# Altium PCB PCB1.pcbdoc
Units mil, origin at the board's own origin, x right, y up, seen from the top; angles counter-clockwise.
Board outline 1325 x 14900.2 mil, 2 copper layers (Top Layer, Bottom Layer); 150 components, 52 nets, 356 pads, 309 vias.
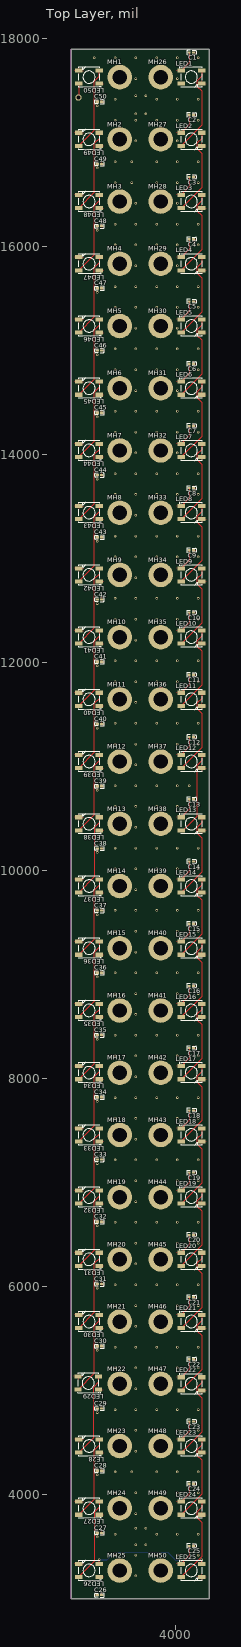
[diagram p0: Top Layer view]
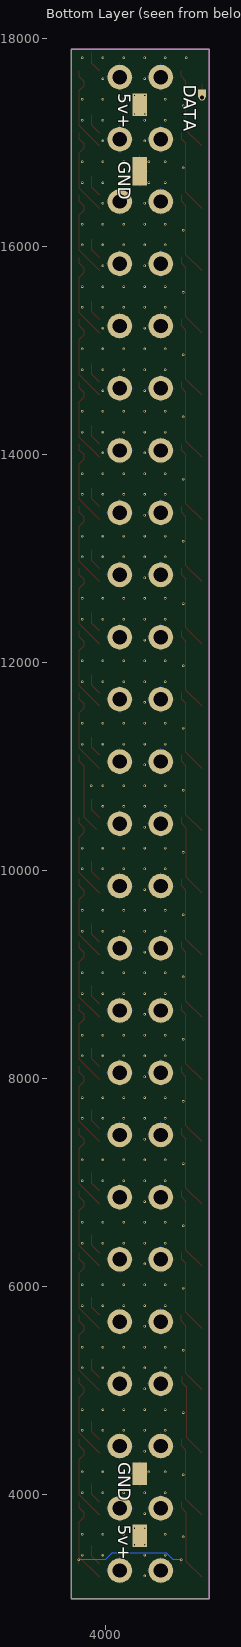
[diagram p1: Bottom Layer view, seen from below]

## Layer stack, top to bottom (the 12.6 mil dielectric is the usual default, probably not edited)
Top Layer: signal copper (thickness not stored)
Dielectric: dielectric 12.6, FR-4, Dk 4.8
Bottom Layer: signal copper (thickness not stored)

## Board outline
3000,17900.2 4325,17900.2 4325,3000 3000,3000

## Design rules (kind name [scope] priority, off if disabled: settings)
BoardOutlineClearance copperThickness1oz [All] p0: genericclearance=10 ignorepadtopadclearanceinfootprint=FALSE except(0: Arc-SplitContinuation Track-SplitContinuation SMDPad-SplitContinuation THPad-SplitContinuation Via-SplitContinuation Fill-SplitContinuation Poly-SplitContinuation Region-SplitContinuation Text-SplitContinuation; 6: Track-CutoutEdge SMDPad-CutoutEdge THPad-CutoutEdge Via-CutoutEdge Region-CutoutEdge; 11.8: Track-OutlineEdge SMDPad-OutlineEdge THPad-OutlineEdge Via-OutlineEdge Fill-OutlineEdge Region-OutlineEdge Poly-OutlineEdge Text-OutlineEdge Fill-CutoutEdge)
BoardOutlineClearance copperThickness2oz [All] p0: genericclearance=10 ignorepadtopadclearanceinfootprint=FALSE except(0: Arc-SplitContinuation Track-SplitContinuation SMDPad-SplitContinuation THPad-SplitContinuation Via-SplitContinuation Fill-SplitContinuation Poly-SplitContinuation Region-SplitContinuation Text-SplitContinuation; 6: Track-CutoutEdge SMDPad-CutoutEdge THPad-CutoutEdge Via-CutoutEdge Region-CutoutEdge; 11.8: Track-OutlineEdge SMDPad-OutlineEdge THPad-OutlineEdge Via-OutlineEdge Fill-OutlineEdge Region-OutlineEdge Poly-OutlineEdge Text-OutlineEdge Fill-CutoutEdge)
Clearance copperThickness1oz [(InNet('+5V') OR InNet('GND') OR InNet('$1N192') OR InNet('$1N362') OR InNet('$1N538') OR InNet('$1N3198') OR InNet('$1N3099') OR InNet('$1N3093') OR InNet('$1N3103') OR InNet('$1N3117') OR InNet('$1N3059') OR InNet('$1N3051') OR InNet('$1N3085') OR InNet('$1N3075') OR InNet('$1N3067') OR InNet('O1') OR InNet('$1N4231') OR InNet('$1N4177') OR InNet('$1N4173') OR InNet('$1N4275') OR InNet('$1N4261') OR InNet('$1N4249') OR InNet('$1N4241') OR InNet('$1N4215') OR InNet('$1N4197') OR InNet('$1N4191') OR InNet('$1N4223') OR InNet('$1N4207') OR InNet('O2') OR InNet('$1N5319') OR InNet('$1N5265') OR InNet('$1N5261') OR InNet('$1N5363') OR InNet('$1N5349') OR InNet('$1N5337') OR InNet('$1N5329') OR InNet('$1N5303') OR InNet('$1N5285') OR InNet('$1N5279') OR InNet('$1N5311') OR InNet('$1N5295') OR InNet('O3') OR InNet('$1N6407') OR InNet('$1N6353') OR InNet('$1N6349') OR InNet('$1N6451') OR InNet('$1N6437') OR InNet('$1N6431') OR InNet('$1N6425') OR InNet('DATA_IN') OR InNet('$1N11195') OR InNet('$1N11396'))] p1: gap=7 ignorepadtopadclearanceinfootprint=FALSE except(4: Track-Track; 6: Track-SMDPad SMDPad-SMDPad Track-THPad SMDPad-THPad THPad-THPad Track-Via SMDPad-Via THPad-Via Via-Via SMDPad-Fill THPad-Fill Via-Fill Fill-Fill Track-Region SMDPad-Region THPad-Region Via-Region Region-Region Track-Poly SMDPad-Poly THPad-Poly Via-Poly Fill-Poly Region-Poly Poly-Poly Track-Text SMDPad-Text THPad-Text Via-Text Fill-Text Region-Text Poly-Text Text-Text; 6.9: Track-Hole SMDPad-Hole THPad-Hole Via-Hole Fill-Hole Region-Hole Poly-Hole Text-Hole Sheet-Hole; 11.8: Track-Fill Fill-Region Track-Sheet SMDPad-Sheet THPad-Sheet Via-Sheet Fill-Sheet Region-Sheet Poly-Sheet Text-Sheet)
Clearance copperThickness2oz [All] p1: gap=7 ignorepadtopadclearanceinfootprint=FALSE except(6: Track-SMDPad SMDPad-SMDPad Track-THPad SMDPad-THPad THPad-THPad Track-Via SMDPad-Via THPad-Via Via-Via SMDPad-Fill THPad-Fill Via-Fill Fill-Fill Track-Region SMDPad-Region THPad-Region Via-Region Region-Region Track-Poly SMDPad-Poly THPad-Poly Via-Poly Fill-Poly Region-Poly Poly-Poly Track-Text SMDPad-Text THPad-Text Via-Text Fill-Text Region-Text Poly-Text Text-Text; 6.9: Track-Hole SMDPad-Hole THPad-Hole Via-Hole Fill-Hole Region-Hole Poly-Hole Text-Hole Sheet-Hole; 8: Track-Track; 11.8: Track-Fill Fill-Region Track-Sheet SMDPad-Sheet THPad-Sheet Via-Sheet Fill-Sheet Region-Sheet Poly-Sheet Text-Sheet)
DiffPairsRouting differentialPair [All] p1: maxuncoupledlength=10 minlimit=6 maxlimit=6 mostfreqgap=6 toplayer_minwidth=5 toplayer_prefwidth=10 toplayer_maxwidth=100 bottomlayer_minwidth=5 bottomlayer_prefwidth=10 bottomlayer_maxwidth=100
PasteMaskExpansion pasteMaskExpansion [All] p1: expansion=0
PlaneConnect innerPlane [All] p1: planeconnectstyle=Relief reliefexpansion=20 reliefentries=4 reliefconductorwidth=10 reliefairgap=10
PolygonConnect copperRegion [All] p1: connectstyle=Relief reliefentries=4 reliefconductorwidth=10 polygonreliefangle="90 Angle" airgapwidth=10
RoutingVias viaSize [All] p1: viastyle="Through Hole" holewidth=12.0078 minholewidth=11.811 maxholewidth=248.0314 width=24.0158 minwidth=19.685 maxwidth=393.7008
SolderMaskExpansion solderMaskExpansion [All] p1: useseparateexpansions=TRUE expansion=2 expansionbottom=2
Width copperThickness1oz [All] p1: maxlimit=100 minlimit=5 preferedwidth=10
Width copperThickness2oz [All] p1: maxlimit=100 minlimit=8 preferedwidth=10

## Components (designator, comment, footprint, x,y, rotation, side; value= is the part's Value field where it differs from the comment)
C1 "CC0402KRX7R7BB104" C0402 4154.41,17869.42 r180 top
C2 "CC0402KRX7R7BB104" C0402 4154.41,17270.97 r180 top
C3 "CC0402KRX7R7BB104" C0402 4154.44,16672.57 r180 top
C4 "CC0402KRX7R7BB104" C0402 4154.41,16074.07 r180 top
C5 "CC0402KRX7R7BB104" C0402 4154.41,15475.62 r180 top
C6 "CC0402KRX7R7BB104" C0402 4154.44,14877.29 r180 top
C7 "CC0402KRX7R7BB104" C0402 4154.44,14278.87 r180 top
C8 "CC0402KRX7R7BB104" C0402 4154.44,13680.44 r180 top
C9 "CC0402KRX7R7BB104" C0402 4154.44,13082.02 r180 top
C10 "CC0402KRX7R7BB104" C0402 4154.44,12483.59 r180 top
C11 "CC0402KRX7R7BB104" C0402 4154.41,11884.91 r180 top
C12 "CC0402KRX7R7BB104" C0402 4154.41,11286.46 r180 top
C13 "CC0402KRX7R7BB104" C0402 4154.41,10688.01 r180 top
C14 "CC0402KRX7R7BB104" C0402 4154.41,10089.56 r180 top
C15 "CC0402KRX7R7BB104" C0402 4154.44,9491.46 r180 top
C16 "CC0402KRX7R7BB104" C0402 4154.44,8893.04 r180 top
C17 "CC0402KRX7R7BB104" C0402 4154.44,8294.61 r180 top
C18 "CC0402KRX7R7BB104" C0402 4154.41,7695.76 r180 top
C19 "CC0402KRX7R7BB104" C0402 4154.41,7097.31 r180 top
C20 "CC0402KRX7R7BB104" C0402 4154.41,6498.86 r180 top
C21 "CC0402KRX7R7BB104" C0402 4154.41,5900.41 r180 top
C22 "CC0402KRX7R7BB104" C0402 4154.44,5302.49 r180 top
C23 "CC0402KRX7R7BB104" C0402 4154.44,4704.06 r180 top
C24 "CC0402KRX7R7BB104" C0402 4154.44,4105.64 r180 top
C25 "CC0402KRX7R7BB104" C0402 4154.44,3507.21 r180 top
C26 "CC0402KRX7R7BB104" C0402 3270.25,3034.17 r0 top
C27 "CC0402KRX7R7BB104" C0402 3270.25,3632.62 r0 top
C28 "CC0402KRX7R7BB104" C0402 3270.25,4231.07 r0 top
C29 "CC0402KRX7R7BB104" C0402 3270.25,4829.52 r0 top
C30 "CC0402KRX7R7BB104" C0402 3270.25,5427.97 r0 top
C31 "CC0402KRX7R7BB104" C0402 3270.25,6026.42 r0 top
C32 "CC0402KRX7R7BB104" C0402 3270.25,6624.87 r0 top
C33 "CC0402KRX7R7BB104" C0402 3270.25,7223.32 r0 top
C34 "CC0402KRX7R7BB104" C0402 3270.25,7821.77 r0 top
C35 "CC0402KRX7R7BB104" C0402 3270.25,8420.22 r0 top
C36 "CC0402KRX7R7BB104" C0402 3270.25,9018.67 r0 top
C37 "CC0402KRX7R7BB104" C0402 3270.25,9617.12 r0 top
C38 "CC0402KRX7R7BB104" C0402 3270.25,10215.57 r0 top
C39 "CC0402KRX7R7BB104" C0402 3270.25,10814.02 r0 top
C40 "CC0402KRX7R7BB104" C0402 3270.25,11412.47 r0 top
C41 "CC0402KRX7R7BB104" C0402 3270.25,12010.92 r0 top
C42 "CC0402KRX7R7BB104" C0402 3270.25,12609.37 r0 top
C43 "CC0402KRX7R7BB104" C0402 3270.25,13207.82 r0 top
C44 "CC0402KRX7R7BB104" C0402 3270.25,13806.27 r0 top
C45 "CC0402KRX7R7BB104" C0402 3270.25,14404.72 r0 top
C46 "CC0402KRX7R7BB104" C0402 3270.25,15003.17 r0 top
C47 "CC0402KRX7R7BB104" C0402 3270.25,15601.63 r0 top
C48 "CC0402KRX7R7BB104" C0402 3270.25,16200.08 r0 top
C49 "CC0402KRX7R7BB104" C0402 3270.25,16798.53 r0 top
C50 "CC0402KRX7R7BB104" C0402 3270.25,17396.98 r0 top
LE28 "WS2812B-V5/W" LED-SMD_4P-L5.0-W5.0-TL-1 3170.2,4468.4 r180 top
LED1 "WS2812B-V5/W" LED-SMD_4P-L5.0-W5.0-TL-1 4154.39,17633.2 r0 top
LED2 "WS2812B-V5/W" LED-SMD_4P-L5.0-W5.0-TL-1 4154.39,17034.8 r0 top
LED3 "WS2812B-V5/W" LED-SMD_4P-L5.0-W5.0-TL-1 4154.39,16436.4 r0 top
LED4 "WS2812B-V5/W" LED-SMD_4P-L5.0-W5.0-TL-1 4154.39,15838 r0 top
LED5 "WS2812B-V5/W" LED-SMD_4P-L5.0-W5.0-TL-1 4154.39,15239.6 r0 top
LED6 "WS2812B-V5/W" LED-SMD_4P-L5.0-W5.0-TL-1 4154.39,14641.2 r0 top
LED7 "WS2812B-V5/W" LED-SMD_4P-L5.0-W5.0-TL-1 4154.39,14042.8 r0 top
LED8 "WS2812B-V5/W" LED-SMD_4P-L5.0-W5.0-TL-1 4154.39,13444.4 r0 top
LED9 "WS2812B-V5/W" LED-SMD_4P-L5.0-W5.0-TL-1 4154.39,12846 r0 top
LED10 "WS2812B-V5/W" LED-SMD_4P-L5.0-W5.0-TL-1 4154.39,12247.6 r0 top
LED11 "WS2812B-V5/W" LED-SMD_4P-L5.0-W5.0-TL-1 4154.39,11649.2 r0 top
LED12 "WS2812B-V5/W" LED-SMD_4P-L5.0-W5.0-TL-1 4154.39,11050.8 r0 top
LED13 "WS2812B-V5/W" LED-SMD_4P-L5.0-W5.0-TL-1 4154.39,10452.4 r0 top
LED14 "WS2812B-V5/W" LED-SMD_4P-L5.0-W5.0-TL-1 4154.39,9854 r0 top
LED15 "WS2812B-V5/W" LED-SMD_4P-L5.0-W5.0-TL-1 4154.39,9255.6 r0 top
LED16 "WS2812B-V5/W" LED-SMD_4P-L5.0-W5.0-TL-1 4154.39,8657.2 r0 top
LED17 "WS2812B-V5/W" LED-SMD_4P-L5.0-W5.0-TL-1 4154.39,8058.8 r0 top
LED18 "WS2812B-V5/W" LED-SMD_4P-L5.0-W5.0-TL-1 4154.39,7460.4 r0 top
LED19 "WS2812B-V5/W" LED-SMD_4P-L5.0-W5.0-TL-1 4154.39,6862 r0 top
LED20 "WS2812B-V5/W" LED-SMD_4P-L5.0-W5.0-TL-1 4154.39,6263.6 r0 top
LED21 "WS2812B-V5/W" LED-SMD_4P-L5.0-W5.0-TL-1 4154.39,5665.2 r0 top
LED22 "WS2812B-V5/W" LED-SMD_4P-L5.0-W5.0-TL-1 4154.39,5066.8 r0 top
LED23 "WS2812B-V5/W" LED-SMD_4P-L5.0-W5.0-TL-1 4154.39,4468.4 r0 top
LED24 "WS2812B-V5/W" LED-SMD_4P-L5.0-W5.0-TL-1 4154.39,3870 r0 top
LED25 "WS2812B-V5/W" LED-SMD_4P-L5.0-W5.0-TL-1 4154.39,3271.6 r0 top
LED26 "WS2812B-V5/W" LED-SMD_4P-L5.0-W5.0-TL-1 3170.2,3271.6 r180 top
LED27 "WS2812B-V5/W" LED-SMD_4P-L5.0-W5.0-TL-1 3170.2,3870 r180 top
LED29 "WS2812B-V5/W" LED-SMD_4P-L5.0-W5.0-TL-1 3162.77,5074.23 r180 top
LED30 "WS2812B-V5/W" LED-SMD_4P-L5.0-W5.0-TL-1 3170.2,5665.2 r180 top
LED31 "WS2812B-V5/W" LED-SMD_4P-L5.0-W5.0-TL-1 3170.2,6263.6 r180 top
LED32 "WS2812B-V5/W" LED-SMD_4P-L5.0-W5.0-TL-1 3170.2,6862 r180 top
LED33 "WS2812B-V5/W" LED-SMD_4P-L5.0-W5.0-TL-1 3170.2,7460.4 r180 top
LED34 "WS2812B-V5/W" LED-SMD_4P-L5.0-W5.0-TL-1 3170.2,8058.8 r180 top
LED35 "WS2812B-V5/W" LED-SMD_4P-L5.0-W5.0-TL-1 3170.2,8657.2 r180 top
LED36 "WS2812B-V5/W" LED-SMD_4P-L5.0-W5.0-TL-1 3170.2,9255.6 r180 top
LED37 "WS2812B-V5/W" LED-SMD_4P-L5.0-W5.0-TL-1 3170.2,9854 r180 top
LED38 "WS2812B-V5/W" LED-SMD_4P-L5.0-W5.0-TL-1 3170.2,10452.4 r180 top
LED39 "WS2812B-V5/W" LED-SMD_4P-L5.0-W5.0-TL-1 3170.2,11050.8 r180 top
LED40 "WS2812B-V5/W" LED-SMD_4P-L5.0-W5.0-TL-1 3170.2,11649.2 r180 top
LED41 "WS2812B-V5/W" LED-SMD_4P-L5.0-W5.0-TL-1 3170.2,12247.6 r180 top
LED42 "WS2812B-V5/W" LED-SMD_4P-L5.0-W5.0-TL-1 3170.2,12846 r180 top
LED43 "WS2812B-V5/W" LED-SMD_4P-L5.0-W5.0-TL-1 3170.2,13444.4 r180 top
LED44 "WS2812B-V5/W" LED-SMD_4P-L5.0-W5.0-TL-1 3170.2,14042.8 r180 top
LED45 "WS2812B-V5/W" LED-SMD_4P-L5.0-W5.0-TL-1 3170.2,14641.2 r180 top
LED46 "WS2812B-V5/W" LED-SMD_4P-L5.0-W5.0-TL-1 3170.2,15239.6 r180 top
LED47 "WS2812B-V5/W" LED-SMD_4P-L5.0-W5.0-TL-1 3170.2,15838 r180 top
LED48 "WS2812B-V5/W" LED-SMD_4P-L5.0-W5.0-TL-1 3170.2,16436.4 r180 top
LED49 "WS2812B-V5/W" LED-SMD_4P-L5.0-W5.0-TL-1 3170.2,17034.8 r180 top
LED50 "WS2812B-V5/W" LED-SMD_4P-L5.0-W5.0-TL-1 3170.28,17633.07 r180 top
MH1 "M3_Hole" M3_Hole 3465.55,17633.07 r0 top
MH2 "M3_Hole" M3_Hole 3465.55,17034.65 r0 top
MH3 "M3_Hole" M3_Hole 3465.55,16436.22 r0 top
MH4 "M3_Hole" M3_Hole 3465.55,15837.8 r0 top
MH5 "M3_Hole" M3_Hole 3465.55,15239.37 r0 top
MH6 "M3_Hole" M3_Hole 3465.55,14640.94 r0 top
MH7 "M3_Hole" M3_Hole 3465.55,14042.52 r0 top
MH8 "M3_Hole" M3_Hole 3465.55,13444.09 r0 top
MH9 "M3_Hole" M3_Hole 3465.55,12845.67 r0 top
MH10 "M3_Hole" M3_Hole 3465.55,12247.24 r0 top
MH11 "M3_Hole" M3_Hole 3465.55,11648.82 r0 top
MH12 "M3_Hole" M3_Hole 3465.55,11050.39 r0 top
MH13 "M3_Hole" M3_Hole 3465.55,10451.97 r0 top
MH14 "M3_Hole" M3_Hole 3465.55,9853.54 r0 top
MH15 "M3_Hole" M3_Hole 3465.55,9255.12 r0 top
MH16 "M3_Hole" M3_Hole 3465.55,8656.69 r0 top
MH17 "M3_Hole" M3_Hole 3465.55,8058.27 r0 top
MH18 "M3_Hole" M3_Hole 3465.55,7459.84 r0 top
MH19 "M3_Hole" M3_Hole 3465.55,6861.42 r0 top
MH20 "M3_Hole" M3_Hole 3465.55,6262.99 r0 top
MH21 "M3_Hole" M3_Hole 3465.55,5664.57 r0 top
MH22 "M3_Hole" M3_Hole 3465.55,5066.14 r0 top
MH23 "M3_Hole" M3_Hole 3465.55,4467.72 r0 top
MH24 "M3_Hole" M3_Hole 3465.55,3869.29 r0 top
MH25 "M3_Hole" M3_Hole 3465.55,3270.87 r0 top
MH26 "M3_Hole" M3_Hole 3859.25,17633.07 r0 top
MH27 "M3_Hole" M3_Hole 3859.25,17034.65 r0 top
MH28 "M3_Hole" M3_Hole 3859.25,16436.22 r0 top
MH29 "M3_Hole" M3_Hole 3859.25,15837.8 r0 top
MH30 "M3_Hole" M3_Hole 3859.25,15239.37 r0 top
MH31 "M3_Hole" M3_Hole 3859.25,14640.94 r0 top
MH32 "M3_Hole" M3_Hole 3859.25,14042.52 r0 top
MH33 "M3_Hole" M3_Hole 3859.25,13444.09 r0 top
MH34 "M3_Hole" M3_Hole 3859.25,12845.67 r0 top
MH35 "M3_Hole" M3_Hole 3859.25,12247.24 r0 top
MH36 "M3_Hole" M3_Hole 3859.25,11648.82 r0 top
MH37 "M3_Hole" M3_Hole 3859.25,11050.39 r0 top
MH38 "M3_Hole" M3_Hole 3859.25,10451.97 r0 top
MH39 "M3_Hole" M3_Hole 3859.25,9853.54 r0 top
MH40 "M3_Hole" M3_Hole 3859.25,9255.12 r0 top
MH41 "M3_Hole" M3_Hole 3859.25,8656.69 r0 top
MH42 "M3_Hole" M3_Hole 3859.25,8058.27 r0 top
MH43 "M3_Hole" M3_Hole 3859.25,7459.84 r0 top
MH44 "M3_Hole" M3_Hole 3859.25,6861.42 r0 top
MH45 "M3_Hole" M3_Hole 3859.25,6262.99 r0 top
MH46 "M3_Hole" M3_Hole 3859.25,5664.57 r0 top
MH47 "M3_Hole" M3_Hole 3859.25,5066.14 r0 top
MH48 "M3_Hole" M3_Hole 3859.25,4467.72 r0 top
MH49 "M3_Hole" M3_Hole 3859.25,3869.29 r0 top
MH50 "M3_Hole" M3_Hole 3859.25,3270.87 r0 top

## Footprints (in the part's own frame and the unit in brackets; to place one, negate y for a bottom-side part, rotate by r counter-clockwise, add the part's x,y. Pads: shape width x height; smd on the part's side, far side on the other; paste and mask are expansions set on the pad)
C0402 [mm]
  rect 0.79x0.54 smd: 1(-0.545,0) 2(0.545,0)
  silkscreen extent -1.17,-0.5 1.17,0.5
LED-SMD_4P-L5.0-W5.0-TL-1 [mm]
  rect 1.8x1 smd: 1(-2.5,1.6) 2(-2.5,-1.6) 3(2.5,-1.6) 4(2.5,1.6)
  silkscreen extent -3,-2.5 2.51,2.5
M3_Hole [mm]
  round 6 hole 3.5: 1(0,0)

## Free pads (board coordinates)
  round 60 hole 36: 1(3067.91,17436.23)
  rect 78.74x78.74 smd far side: 1(3067.91,17475.6)
  rect 137.79x216.53 smd far side: 2(3668.3,3603.55) 2(3668.3,4201.98) 2(3668.3,17367.33)
  rect 137.79x275.59 smd far side: 5(3668.3,16727.57)

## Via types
v1: diameter 24.02, hole 12.01, Top Layer to Bottom Layer, 309 vias

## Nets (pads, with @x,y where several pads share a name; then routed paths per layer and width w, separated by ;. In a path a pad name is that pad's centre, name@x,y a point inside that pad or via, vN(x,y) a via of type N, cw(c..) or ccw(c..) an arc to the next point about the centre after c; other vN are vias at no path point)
$1N192: LED1.4 LED2.2 | length 844.4
  Top Layer w10: LED2.2 4252.81,17168.66 4252.81,17499.55 4206.4,17545.97 4206.4,17594.44 4252.81,17640.86 LED1.4
$1N362: LED2.4 LED3.2 | length 844.4
  Top Layer w10: LED3.2 4252.81,16570.26 4252.81,16901.15 4206.4,16947.57 4206.4,16996.04 4252.81,17042.46 LED2.4
$1N538: LED3.4 LED4.2 | length 844.4
  Top Layer w10: LED4.2 4252.81,15971.86 4252.81,16302.75 4206.4,16349.17 4206.4,16397.64 4252.81,16444.06 LED3.4
$1N3051: LED10.4 LED11.2 | length 844.4
  Top Layer w10: LED11.2 4252.81,11783.06 4252.81,12113.95 4206.4,12160.37 4206.4,12208.84 4252.81,12255.26 LED10.4
$1N3059: LED9.4 LED10.2 | length 844.4
  Top Layer w10: LED10.2 4252.81,12381.46 4252.81,12712.35 4206.4,12758.77 4206.4,12807.24 4252.81,12853.66 LED9.4
$1N3067: LED13.4 LED14.2 | length 844.4
  Top Layer w10: LED14.2 4252.81,9987.86 4252.81,10318.75 4206.4,10365.17 4206.4,10413.64 4252.81,10460.06 LED13.4
$1N3075: LED12.4 LED13.2 | length 782.8
  Top Layer w10: LED13.2@4085.79,10400.2 4206.4,10520.8 4206.4,11012.04 4252.81,11058.46 LED12.4
$1N3085: LED11.4 LED12.2 | length 844.4
  Top Layer w10: LED12.2 4252.81,11184.66 4252.81,11515.55 4206.4,11561.97 4206.4,11610.44 4252.81,11656.86 LED11.4
$1N3093: LED6.4 LED7.2 | length 844.4
  Top Layer w10: LED7.2 4252.81,14176.66 4252.81,14507.55 4206.4,14553.97 4206.4,14602.44 4252.81,14648.86 LED6.4
$1N3099: LED5.4 LED6.2 | length 844.4
  Top Layer w10: LED6.2 4252.81,14775.06 4252.81,15105.95 4206.4,15152.37 4206.4,15200.84 4252.81,15247.26 LED5.4
$1N3103: LED7.4 LED8.2 | length 844.4
  Top Layer w10: LED8.2 4252.81,13578.26 4252.81,13909.15 4206.4,13955.57 4206.4,14004.04 4252.81,14050.46 LED7.4
$1N3117: LED8.4 LED9.2 | length 844.4
  Top Layer w10: LED9.2 4252.81,12979.86 4252.81,13310.75 4206.4,13357.17 4206.4,13405.64 4252.81,13452.06 LED8.4
$1N3198: LED4.4 LED5.2 | length 844.4
  Top Layer w10: LED5.2 4252.81,15373.46 4252.81,15704.35 4206.4,15750.77 4206.4,15799.24 4252.81,15845.66 LED4.4
$1N4173: LED17.4 LED18.2 | length 844.4
  Top Layer w10: LED18.2 4252.81,7594.26 4252.81,7925.15 4206.4,7971.57 4206.4,8020.04 4252.81,8066.46 LED17.4
$1N4177: LED16.4 LED17.2 | length 844.4
  Top Layer w10: LED17.2 4252.81,8192.66 4252.81,8523.55 4206.4,8569.97 4206.4,8618.44 4252.81,8664.86 LED16.4
$1N4191: LED24.4 LED25.2 | length 844.4
  Top Layer w10: LED25.2 4252.81,3405.46 4252.81,3736.35 4206.4,3782.77 4206.4,3831.24 4252.81,3877.66 LED24.4
$1N4197: LED23.4 LED24.2 | length 844.4
  Top Layer w10: LED24.2 4252.81,4003.86 4252.81,4334.75 4206.4,4381.17 4206.4,4429.64 4252.81,4476.06 LED23.4
$1N4207: LED25.4 LED26.2 | length 1119.7
  Top Layer w10: LED26.2 v1(3268.62,3373.96) ; LED25.4 4252.81,3372.94 v1(4253.32,3373.45)
  Bottom Layer w10: v1(3268.62,3373.96) 3343.17,3373.96 3411.2,3441.99 3932.25,3441.99 4000.28,3373.96 4252.81,3373.96 v1(4253.32,3373.45)
$1N4215: LED22.4 LED23.2 | length 844.4
  Top Layer w10: LED23.2 4252.81,4602.26 4252.81,4933.15 4206.4,4979.57 4206.4,5028.04 4252.81,5074.46 LED22.4
$1N4223: LED26.4 LED27.2 | length 805.9
  Top Layer w10: LED26.4 3222.21,3359.04 3222.21,3831.24 3268.62,3877.66 LED27.2
$1N4231: LED15.4 LED16.2 | length 844.4
  Top Layer w10: LED16.2 4252.81,8791.06 4252.81,9121.95 4206.4,9168.37 4206.4,9216.84 4252.81,9263.26 LED15.4
$1N4241: LED21.4 LED22.2 | length 844.4
  Top Layer w10: LED22.2 4252.81,5200.66 4252.81,5531.55 4206.4,5577.97 4206.4,5626.44 4252.81,5672.86 LED21.4
$1N4249: LED20.4 LED21.2 | length 844.4
  Top Layer w10: LED21.2 4252.81,5799.06 4252.81,6129.95 4206.4,6176.37 4206.4,6224.84 4252.81,6271.26 LED20.4
$1N4261: LED19.4 LED20.2 | length 844.4
  Top Layer w10: LED20.2 4252.81,6397.46 4252.81,6728.35 4206.4,6774.77 4206.4,6823.24 4252.81,6869.66 LED19.4
$1N4275: LED18.4 LED19.2 | length 844.4
  Top Layer w10: LED19.2 4252.81,6995.86 4252.81,7326.75 4206.4,7373.17 4206.4,7421.64 4252.81,7468.06 LED18.4
$1N5261: LED31.4 LED32.2 | length 805.9
  Top Layer w10: LED31.4 3222.21,6351.04 3222.21,6823.24 3268.62,6869.66 LED32.2
$1N5265: LED30.4 LED31.2 | length 805.9
  Top Layer w10: LED30.4 3222.21,5752.64 3222.21,6224.84 3268.62,6271.26 LED31.2
$1N5279: LED38.4 LED39.2 | length 805.9
  Top Layer w10: LED38.4 3222.21,10539.84 3222.21,11012.04 3268.62,11058.46 LED39.2
$1N5285: LED37.4 LED38.2 | length 805.9
  Top Layer w10: LED37.4 3222.21,9941.44 3222.21,10413.64 3268.62,10460.06 LED38.2
$1N5295: LED39.4 LED40.2 | length 805.9
  Top Layer w10: LED39.4 3222.21,11138.24 3222.21,11610.44 3268.62,11656.86 LED40.2
$1N5303: LED36.4 LED37.2 | length 805.9
  Top Layer w10: LED36.4 3222.21,9343.04 3222.21,9815.24 3268.62,9861.66 LED37.2
$1N5311: LED40.4 LED41.2 | length 805.9
  Top Layer w10: LED40.4 3222.21,11736.64 3222.21,12208.84 3268.62,12255.26 LED41.2
$1N5319: LED29.4 LED30.2 | length 801.6
  Top Layer w10: LED29.4 3222.21,5169.1 3222.21,5626.44 3268.62,5672.86 LED30.2
$1N5329: LED35.4 LED36.2 | length 805.9
  Top Layer w10: LED35.4 3222.21,8744.64 3222.21,9216.84 3268.62,9263.26 LED36.2
$1N5337: LED34.4 LED35.2 | length 805.9
  Top Layer w10: LED34.4 3222.21,8146.24 3222.21,8618.44 3268.62,8664.86 LED35.2
$1N5349: LED33.4 LED34.2 | length 805.9
  Top Layer w10: LED33.4 3222.21,7547.84 3222.21,8020.04 3268.62,8066.46 LED34.2
$1N5363: LED32.4 LED33.2 | length 805.9
  Top Layer w10: LED32.4 3222.21,6949.44 3222.21,7421.64 3268.62,7468.06 LED33.2
$1N6349: LED45.4 LED46.2 | length 805.9
  Top Layer w10: LED45.4 3222.21,14728.64 3222.21,15200.84 3268.62,15247.26 LED46.2
$1N6353: LED44.4 LED45.2 | length 805.9
  Top Layer w10: LED44.4 3222.21,14130.24 3222.21,14602.44 3268.62,14648.86 LED45.2
$1N6407: LED43.4 LED44.2 | length 805.9
  Top Layer w10: LED43.4 3222.21,13531.84 3222.21,14004.04 3268.62,14050.46 LED44.2
$1N6425: LED49.4 LED50.2 | length 805.8
  Top Layer w10: LED49.4 3222.25,17122.29 3222.25,17594.29 3268.7,17640.73 LED50.2
$1N6431: LED47.4 LED48.2 | length 805.9
  Top Layer w10: LED47.4 3222.21,15925.44 3222.21,16397.64 3268.62,16444.06 LED48.2
$1N6437: LED48.4 LED49.2 | length 805.9
  Top Layer w10: LED48.4 3222.21,16523.84 3222.21,16996.04 3268.62,17042.46 LED49.2
$1N6451: LED46.4 LED47.2 | length 805.9
  Top Layer w10: LED46.4 3222.21,15327.04 3222.21,15799.24 3268.62,15845.66 LED47.2
$1N11195: LE28.2 LED27.4 | length 805.9
  Top Layer w10: LED27.4 3222.21,3957.44 3222.21,4429.64 3268.62,4476.06 LE28.2
$1N11396: LED41.4 LED42.2 | length 805.9
  Top Layer w10: LED41.4 3222.21,12335.04 3222.21,12807.24 3268.62,12853.66 LED42.2
+5V: C1.2 C2.2 C3.2 C4.2 C5.2 C6.2 C7.2 C8.2 C9.2 C10.2 C11.2 C12.2 C13.2 C14.2 C15.2 C16.2 C17.2 C18.2 C19.2 C20.2 C21.2 C22.2 C23.2 C24.2 C25.2 C26.2 C27.2 C28.2 C29.2 C30.2 C31.2 C32.2 C33.2 C34.2 C35.2 C36.2 C37.2 C38.2 C39.2 C40.2 C41.2 C42.2 C43.2 C44.2 C45.2 C46.2 C47.2 C48.2 C49.2 C50.2 LE28.1 LED1.1 LED2.1 LED3.1 LED4.1 LED5.1 LED6.1 LED7.1 LED8.1 LED9.1 LED10.1 LED11.1 LED12.1 LED13.1 LED14.1 LED15.1 LED16.1 LED17.1 LED18.1 LED19.1 LED20.1 LED21.1 LED22.1 LED23.1 LED24.1 LED25.1 LED26.1 LED27.1 LED29.1 LED30.1 LED31.1 LED32.1 LED33.1 LED34.1 LED35.1 LED36.1 LED37.1 LED38.1 LED39.1 LED40.1 LED41.1 LED42.1 LED43.1 LED44.1 LED45.1 LED46.1 LED47.1 LED48.1 LED49.1 LED50.1 pad.2@3668.3,3603.55 pad.2@3668.3,17367.33 | length 5117.4
  Top Layer w10: LED25.1 4132.98,3411.6 C25.2 ; LED24.1 4132.98,4010 C24.2 ; LED23.1 4132.98,4608.4 C23.2 ; LED22.1 4132.98,5206.8 C22.2 ; LED21.1 4132.95,5805.18 C21.2 ; LED20.1 4132.95,6403.58 C20.2 ; LED19.1 4132.95,7001.98 C19.2 ; LED18.1 4132.95,7600.38 C18.2 ; LED17.1 4132.98,8198.8 C17.2 ; LED16.1 4132.98,8797.2 C16.2 ; LED15.1 4132.98,9395.6 C15.2 ; LED14.1 4132.95,9993.98 C14.2 ; LED13.1 4132.95,10592.38 C13.2 ; LED12.1 4132.95,11190.78 C12.2 ; LED11.1 4132.95,11789.18 C11.2 ; LED10.1 4132.98,12387.6 C10.2 ; LED9.1 4132.98,12986 C9.2 ; LED8.1 4132.98,13584.4 C8.2 ; LED7.1 4132.98,14182.8 C7.2 ; LED6.1 4132.98,14781.2 C6.2 ; LED5.1 4132.95,15379.58 C5.2 ; LED4.1 4132.95,15977.98 C4.2 ; LED3.1 4132.98,16576.4 C3.2 ; LED2.1 4132.95,17174.78 C2.2 ; LED1.1 4132.95,17773.18 C1.2
  other v1: 3619.09,3518.93 3717.51,3518.93 3619.09,3676.41 3717.51,3676.41 3619.09,17278.75 3717.51,17278.75 3619.09,17455.91 3717.51,17455.91
DATA_IN: LED50.4 pad.1 | length 135.5
  Top Layer w10: pad.1@3067.91,17436.23 3071.85,17440.17 LED50.4
GND: C1.1 C2.1 C3.1 C4.1 C5.1 C6.1 C7.1 C8.1 C9.1 C10.1 C11.1 C12.1 C13.1 C14.1 C15.1 C16.1 C17.1 C18.1 C19.1 C20.1 C21.1 C22.1 C23.1 C24.1 C25.1 C26.1 C27.1 C28.1 C29.1 C30.1 C31.1 C32.1 C33.1 C34.1 C35.1 C36.1 C37.1 C38.1 C39.1 C40.1 C41.1 C42.1 C43.1 C44.1 C45.1 C46.1 C47.1 C48.1 C49.1 C50.1 LE28.3 LED1.3 LED2.3 LED3.3 LED4.3 LED5.3 LED6.3 LED7.3 LED8.3 LED9.3 LED10.3 LED11.3 LED12.3 LED13.3 LED14.3 LED15.3 LED16.3 LED17.3 LED18.3 LED19.3 LED20.3 LED21.3 LED22.3 LED23.3 LED24.3 LED25.3 LED26.3 LED27.3 LED29.3 LED30.3 LED31.3 LED32.3 LED33.3 LED34.3 LED35.3 LED36.3 LED37.3 LED38.3 LED39.3 LED40.3 LED41.3 LED42.3 LED43.3 LED44.3 LED45.3 LED46.3 LED47.3 LED48.3 LED49.3 LED50.3 MH1.1 MH2.1 MH3.1 MH4.1 MH5.1 MH6.1 MH7.1 MH8.1 MH9.1 MH10.1 MH11.1 MH12.1 MH13.1 MH14.1 MH15.1 MH16.1 MH17.1 MH18.1 MH19.1 MH20.1 MH21.1 MH22.1 MH23.1 MH24.1 MH25.1 MH26.1 MH27.1 MH28.1 MH29.1 MH30.1 MH31.1 MH32.1 MH33.1 MH34.1 MH35.1 MH36.1 MH37.1 MH38.1 MH39.1 MH40.1 MH41.1 MH42.1 MH43.1 MH44.1 MH45.1 MH46.1 MH47.1 MH48.1 MH49.1 MH50.1 pad.2@3668.3,4201.98 pad.5
  other v1: 3620.73,3219 3420.73,3419 3620.73,3419 3820.73,3419 4020.73,3419 4220.73,3419 3248.79,3593.25 3420.73,3619 3820.73,3619 4020.73,3619 4220.73,3619 3620.73,3819 3420.73,4019 3620.73,4019 3820.73,4019 4020.73,4019 4220.73,4019 3248.79,4191.7 3420.73,4219 3581.36,4219 3820.73,4219 4020.73,4219 4220.73,4219 3620.73,4419 3420.73,4619 3620.73,4619 3820.73,4619 4020.73,4619 4220.73,4619 3248.79,4790.15 3420.73,4819 3620.73,4819 3820.73,4819 4020.73,4819 4220.73,4819 3620.73,5019 3420.73,5219 3620.73,5219 3820.73,5219 4020.73,5219 4220.73,5219 3248.79,5388.6 3420.73,5419 3620.73,5419 3820.73,5419 4020.73,5419 4220.73,5419 3620.73,5619 3420.73,5819 3620.73,5819 3820.73,5819 4020.73,5819 4220.73,5819 3248.79,5987.05 3420.73,6019 3620.73,6019 3820.73,6019 4020.73,6019 4220.73,6019 3620.73,6219 3420.73,6419 3620.73,6419 3820.73,6419 4020.73,6419 4220.73,6419 3248.79,6585.5 3420.73,6619 3620.73,6619 3820.73,6619 4020.73,6619 4220.73,6619 3620.73,6819 3420.73,7019 3620.73,7019 3820.73,7019 4020.73,7019 4220.73,7019 3248.79,7183.95 3420.73,7219 3620.73,7219 3820.73,7219 4020.73,7219 4220.73,7219 3620.73,7419 3420.73,7619 3620.73,7619 3820.73,7619 4020.73,7619 4220.73,7619 3248.79,7782.4 3420.73,7819 3620.73,7819 3820.73,7819 4020.73,7819 4220.73,7819 3620.73,8019 3420.73,8219 3620.73,8219 3820.73,8219 4020.73,8219 4220.73,8219 3248.79,8380.85 3420.73,8419 3620.73,8419 3820.73,8419 4020.73,8419 4220.73,8419 3620.73,8619 3420.73,8819 3620.73,8819 3820.73,8819 4020.73,8819 4220.73,8819 3248.79,8979.3 3420.73,9019 3620.73,9019 3820.73,9019 4020.73,9019 4220.73,9019 3620.73,9219 3420.73,9419 3620.73,9419 3820.73,9419 4020.73,9419 4220.73,9419 3248.79,9577.75 3420.73,9619 3620.73,9619 3820.73,9619 4020.73,9619 4220.73,9619 3620.73,9819 3420.73,10019 3620.73,10019 3820.73,10019 4020.73,10019 4220.73,10019 3248.79,10176.2 3420.73,10219 3620.73,10219 3820.73,10219 4020.73,10219 4220.73,10219 3620.73,10419 3420.73,10619 3620.73,10619 3820.73,10619 4020.73,10619 3248.79,10774.65 3420.73,10819 3620.73,10819 3820.73,10819 4020.73,10819 4133.67,10819 3620.73,11019 3420.73,11219 3620.73,11219 3820.73,11219 4020.73,11219 4220.73,11219 3248.79,11373.1 3420.73,11419 3620.73,11419 3820.73,11419 4020.73,11419 4220.73,11419 3620.73,11619 3420.73,11819 3620.73,11819 3820.73,11819 4020.73,11819 4220.73,11819 3248.79,11971.55 3420.73,12019 3620.73,12019 3820.73,12019 4020.73,12019 4220.73,12019 3620.73,12219 3420.73,12419 3620.73,12419 3820.73,12419 4020.73,12419 4220.73,12419 3248.79,12570 3420.73,12619 3620.73,12619 3820.73,12619 4020.73,12619 4220.73,12619 3620.73,12819 3420.73,13019 3620.73,13019 3820.73,13019 4020.73,13019 4220.73,13019 3248.79,13168.45 3420.73,13219 3620.73,13219 3820.73,13219 4020.73,13219 4220.73,13219 3620.73,13419 3420.73,13619 3620.73,13619 3820.73,13619 4020.73,13619 4220.73,13619 3248.79,13766.9 3420.73,13819 3620.73,13819 3820.73,13819 4020.73,13819 4220.73,13819 3620.73,14019 4020.73,14019 3420.73,14219 3620.73,14219 3820.73,14219 4020.73,14219 4220.73,14219 3248.79,14365.35 3420.73,14419 3620.73,14419 3820.73,14419 4020.73,14419 4220.73,14419 3620.73,14619 4020.73,14619 3420.73,14819 3620.73,14819 3820.73,14819 4020.73,14819 4220.73,14819 3248.79,14963.8 3420.73,15019 3620.73,15019 3820.73,15019 4020.73,15019 4220.73,15019 3620.73,15219 4020.73,15219 3420.73,15419 3620.73,15419 3820.73,15419 4020.73,15419 4220.73,15419 3248.79,15562.26 3420.73,15619 3620.73,15619 3820.73,15619 4020.73,15619 4220.73,15619 3620.73,15819 4020.73,15819 3420.73,16019 3620.73,16019 3820.73,16019 4020.73,16019 4220.73,16019 3248.79,16160.71 3420.73,16219 3620.73,16219 3820.73,16219 4020.73,16219 4220.73,16219 3620.73,16419 4020.73,16419 3420.73,16619 3581.36,16619 3820.73,16619 4020.73,16619 4220.73,16619 3248.79,16759.16 3420.73,16819 3581.36,16819 3820.73,16819 4020.73,16819 4220.73,16819 3620.73,17019 4020.73,17019 3420.73,17219 3620.73,17219 3820.73,17219 4020.73,17219 4220.73,17219 3248.79,17357.61 3420.73,17419 3820.73,17419 4020.73,17419 4220.73,17419 3620.73,17619 4020.73,17619 3220.73,17819 3420.73,17819 3620.73,17819 3820.73,17819 4020.73,17819 4220.73,17819
O1: LED14.4 LED15.2 | length 844.4
  Top Layer w10: LED15.2 4252.81,9389.46 4252.81,9720.35 4206.4,9766.77 4206.4,9815.24 4252.81,9861.66 LED14.4
O2: LE28.4 LED29.2 | length 810.3
  Top Layer w10: LE28.4 3214.78,4548.41 3214.78,5035.48 3261.2,5081.89 LED29.2
O3: LED42.4 LED43.2 | length 805.9
  Top Layer w10: LED42.4 3222.21,12933.44 3222.21,13405.64 3268.62,13452.06 LED43.2
pads on no net: LED1.2

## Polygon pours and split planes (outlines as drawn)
+5V on Top Layer (solid, remove dead copper, pour order 0): 3268.7,17892.92 4056.1,17892.92 4056.1,3015 3268.7,3015
GND on Top Layer (solid, remove dead copper, pour order 2): 3008.86,17892.92 3268.7,17892.92 3268.7,3018.93 3008.86,3018.93
GND on Top Layer (solid, remove dead copper, pour order 4): 4056.1,17892.92 4315.94,17892.92 4315.94,3015 4056.1,3015
GND on Bottom Layer (solid, remove dead copper, pour order 6): 3016.73,17888.98 4310.04,17888.98 4310.04,3015 3016.73,3015

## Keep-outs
Board Outline Layer:
  the board outline again, w10

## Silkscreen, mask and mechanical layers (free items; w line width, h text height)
Bottom Silkscreen Layer:
  text "DATA" at 3246.02,17561.71 h120 r90
  text "5v+" at 3874.99,17475.6 h120 r90
  text "GND" at 3874.99,16825.99 h120 r90
  text "GND" at 3874.99,4310.24 h120 r90
  text "5v+" at 3874.99,3711.82 h120 r90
